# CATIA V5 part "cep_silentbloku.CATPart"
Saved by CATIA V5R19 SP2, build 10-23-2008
Part number: cep_silentbloku
Bounding box of the stored display mesh (mm): x -34.99 to 34.99, y -85 to 85, z -34.986 to 34.986
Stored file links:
  D:\Catia fórum\Modely - Otazky\Naklapeni_oprava\cep_silentbloku.CATPart
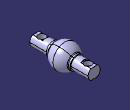
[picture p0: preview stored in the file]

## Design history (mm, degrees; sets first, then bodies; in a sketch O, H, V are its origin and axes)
Body1 (main body)
  Sketch1 on yz-plane, origin (0, 0, 0), H (0, 1, 0), V (0, 0, 1)
    arc A1 centre (0, 0) radius 35 from (0, 35) to (-27.8609, 21.1842) ccw
    point P1 (-35, 20)
    line L1 (-35, 20) -> (-30.249, 20)
    line L2 (-35, 0) -> (-35, 20)
    arc A2 centre (-30.249, 23) radius 3 from (-27.8609, 21.1842) to (-30.249, 20) cw
    point P2 (-27.8609, 21.1842)
    point P3 (-30.249, 20)
    construction line L3 (0, 43.9251) -> (0, -30.2246)
    point P5 (0, 43.9251)
    construction line L4 (-44.9387, 0) -> (49.0391, 0)
    point P7 (-44.9387, 0)
    point P9 (-35, 0)
    point P10 (0, 35)
    construction line L5 through (0, 0) direction (0, 1)
    point P14 (35, 20)
    point P15 (27.8609, 21.1842)
    point P16 (30.249, 20)
    point P18 (44.9387, 0)
    point P19 (35, 0)
    point P20 (0, 35)
    arc A3 centre (0, 0) radius 35 from (0, 35) to (27.8609, 21.1842) cw
    line L6 (35, 20) -> (30.249, 20)
    line L7 (35, 0) -> (35, 20)
    arc A4 centre (30.249, 23) radius 3 from (27.8609, 21.1842) to (30.249, 20) ccw
    axis line L8 (-50.4914, 0) -> (55.8491, 0)
    radius A1 = 35
    distance H L1 = 20
    distance V L2 = 35
    radius A2 = 3
    horizontal: L1 H, L4 H, L8 H
    vertical: L2 V, L3 V
    tangency: A2 A1, A2 L1
    coincidence: P5 V, P7 H, L4 P9, L3 P10, P10 P20
    symmetry: V L5 L3, P1 P14 L3, P2 P15 L3, P3 P16 L3, P7 P18 L3, P9 P19 L3, P10 P20 L3, A1 A3 L3, L1 L6 L3, L2 L7 L3, A2 A4 L3
  Shaft1: profile Sketch1, axis Sketch1.L8, angle 360
  Sketch2 on face of Shaft1 from Sketch1.L7, origin (0, 35, 0), H (-1, 0, 0), V (0, 0, 1)
    circle A1 centre (0, 0) radius 17.5
    point P1 (0, 17.5)
    radius A1 = 17.5
    coincidence: A1 P1, P1 V
  Pad1: profile Sketch2, direction (0, 1, 0), length 50
  Sketch3 on end face of Pad1, origin (0, 85, 0), H (-1, 0, 0), V (0, 0, 1)
    line L1 (-9.0139, 15) -> (9.0139, 15)
    arc A1 centre (0, 0) radius 17.5 from (9.0139, 15) to (-9.0139, 15) ccw
    point P1 (-9.0139, 15)
    point P2 (9.0139, 15)
    construction line L2 (6.0834, 0) -> (36.3656, 0)
    point P3 (6.0834, 0)
    point P5 (-9.0139, -15)
    point P6 (9.0139, -15)
    line L3 (-9.0139, -15) -> (9.0139, -15)
    arc A2 centre (0, 0) radius 17.5 from (9.0139, -15) to (-9.0139, -15) cw
    radius A1 = 17.5
    distance H L1 = 15
    horizontal: L1 H, L2 H
    coincidence: P3 H
    symmetry: P1 P5 L2, P2 P6 L2, L1 L3 L2, A1 A2 L2
  Pocket1: profile Sketch3, direction (0, -1, 0), length 30
  Sketch4 on face of Pocket1 from Sketch3.L1, origin (0, 0, 15), H (1, 0, 0), V (0, 1, 0)
    point P1 (0, 67.5)
    reference projected line E1 (9.0139, 85) -> (-9.0139, 85) from edge [end face of Pad1 | face of Pocket1 from Sketch3.L1]
    distance P1 E1 = 17.5
    coincidence: P1 V
  Sketch5 on face of Pocket1 from Sketch3.L1, origin (0, 67.5, 15), H (1, 0, 0), V (0, 1, 0)
    point P1 (0, 0)
    reference projected line E1 (-35, -67.5) -> (35, -67.5) from edge [face of Shaft1 from Sketch1.A1 | face of Shaft1 from Sketch1.A3]
    distance P1 E1 = 67.5
  Hole1: placed by Sketch5, at (0, 67.5, 15) direction (0, 0, -1), diameter 21, through (limit type 6)
  Mirror1: of Pad1, Pocket1, Hole1, about zx-plane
